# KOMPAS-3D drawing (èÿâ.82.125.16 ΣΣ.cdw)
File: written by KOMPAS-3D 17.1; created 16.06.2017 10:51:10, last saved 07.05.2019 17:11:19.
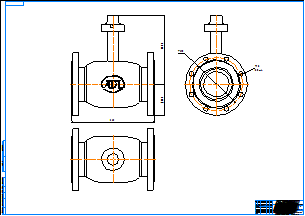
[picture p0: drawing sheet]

Sheet 1: A0, landscape

Title block, sheet 1: name: КШГ.82.125.16 фф; material: Внимание! Данный продукт является объектом авторского права ООО «Торговый Дом АДЛ». / Запрещается изменение, копирование, распространение / (в том числе путем копирования на другие сайты и ресурсы в Интернете) / или любое иное использование информации и объектов без предварительного / согласия правообладателя (ООО «Торговый Дом АДЛ»).; scale: 1:1; sheets: 1; organisation: ООО "Торговый дом АДЛ"; sheet format: A0; stored path: C:\Users\tra\Desktop\2д чертежи\Шаровые краны БИВАЛ\КШ_Бивал_серия_82_85\KOMPAS 2D\КШГ.82.125.16 фф.cdw

Views: Спереди 1, Проекционный вид 2, Проекционный вид 3
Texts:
  Klimkovich
  ADL
Dimensions and other numbers on the sheet: 325; 266,9; 122,5; 210; 18; 8 Отв.; 1:1; 1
